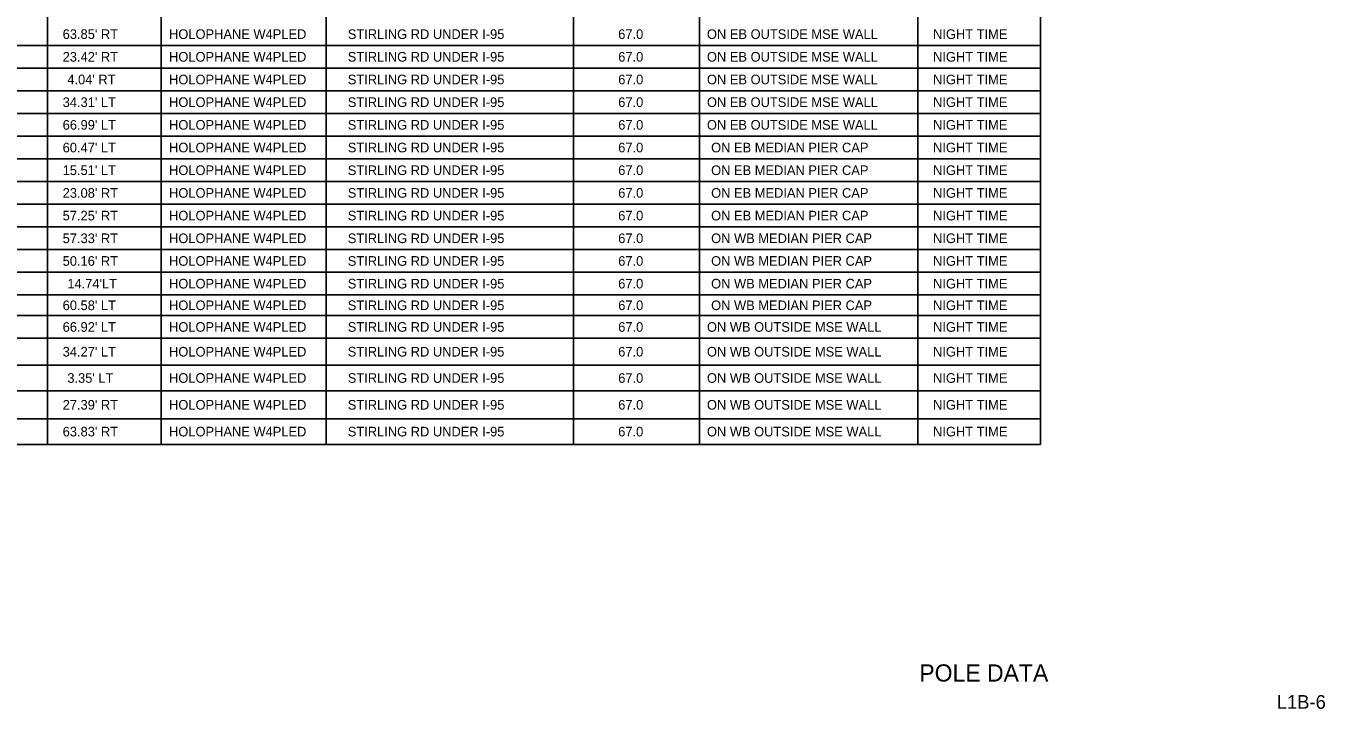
# Model space of a CAD drawing. Extents: x -816.7 to -800.9, y -2209.6 to -2187.8.
# Drawn here: x -810.38 to -800.93, y -2197.64 to -2192.68 of the extents above; entities that cross this region are included whole.
import ezdxf

# ---------------------------------------------------------------- set-up
doc = ezdxf.new("R2010")
doc.units = 0
for name, color, linetype in [('PlotBorder_dp', 7, 'Continuous'), ('SheetBorder_dp', 7, 'Continuous'), ('SheetLines_dp', 7, 'Continuous'), ('TextMinor', 7, 'Continuous'), ('TextMisc', 7, 'Continuous'), ('TextShtNo', 7, 'Continuous')]:
    doc.layers.add(name, color=color, linetype=linetype)

msp = doc.modelspace()

# ---------------------------------------------------------------- linework, layer by layer
at = {"layer": 'PlotBorder_dp'}
for p, q in [((-810.2186, -2188.1983), (-810.2186, -2195.7208)), ((-809.3936, -2188.1983), (-809.3936, -2195.7208)), ((-809.3936, -2188.1983), (-809.3936, -2195.7208)), ((-808.1936, -2188.1983), (-808.1936, -2195.7208)), ((-808.1936, -2188.1983), (-808.1936, -2195.7208)), ((-806.3936, -2188.1983), (-806.3936, -2195.7208)), ((-806.3936, -2188.1983), (-806.3936, -2195.7208)), ((-805.4786, -2188.1983), (-805.4786, -2195.7208)), ((-805.4786, -2188.1983), (-805.4786, -2195.7208)), ((-810.2186, -2189.5183), (-810.2186, -2195.7208))]:
    msp.add_line(p, q, dxfattribs=at)
at = {"layer": 'SheetLines_dp'}
for p, q in [((-802.9961, -2187.8233), (-802.9961, -2195.7208)), ((-803.8886, -2188.1983), (-803.8886, -2195.7208)), ((-803.8886, -2188.1983), (-803.8886, -2195.7208)), ((-813.0161, -2195.7208), (-802.9961, -2195.7208))]:
    msp.add_line(p, q, dxfattribs=at)
at = {"layer": 'TextMinor'}
for p, q in [((-813.0161, -2192.8183), (-802.9961, -2192.8183)), ((-813.0161, -2192.8183), (-802.9961, -2192.8183)), ((-813.0161, -2192.9833), (-802.9961, -2192.9833)), ((-813.0161, -2192.9833), (-802.9961, -2192.9833)), ((-813.0161, -2193.1483), (-802.9961, -2193.1483)), ((-813.0161, -2193.1483), (-802.9961, -2193.1483)), ((-813.0161, -2193.3133), (-802.9961, -2193.3133)), ((-813.0161, -2193.3133), (-802.9961, -2193.3133)), ((-813.0161, -2193.4783), (-802.9961, -2193.4783)), ((-813.0161, -2193.4783), (-802.9961, -2193.4783)), ((-813.0161, -2193.6433), (-802.9961, -2193.6433)), ((-813.0161, -2193.6433), (-802.9961, -2193.6433)), ((-813.0161, -2193.8083), (-802.9961, -2193.8083)), ((-813.0161, -2193.8083), (-802.9961, -2193.8083)), ((-813.0161, -2193.9733), (-802.9961, -2193.9733)), ((-813.0161, -2193.9733), (-802.9961, -2193.9733)), ((-813.0161, -2194.1383), (-802.9961, -2194.1383)), ((-813.0161, -2194.1383), (-802.9961, -2194.1383)), ((-813.0161, -2194.3033), (-802.9961, -2194.3033)), ((-813.0161, -2194.3033), (-802.9961, -2194.3033)), ((-813.0161, -2194.4683), (-802.9961, -2194.4683)), ((-813.0161, -2194.4683), (-802.9961, -2194.4683)), ((-813.0161, -2194.6333), (-802.9961, -2194.6333)), ((-813.0161, -2194.6333), (-802.9961, -2194.6333)), ((-813.0161, -2194.7833), (-802.9961, -2194.7833)), ((-813.0161, -2194.7833), (-802.9961, -2194.7833)), ((-813.0161, -2194.9483), (-802.9961, -2194.9483)), ((-813.0161, -2194.9483), (-802.9961, -2194.9483)), ((-813.0161, -2195.1433), (-802.9961, -2195.1433)), ((-813.0161, -2195.1433), (-802.9961, -2195.1433)), ((-813.0161, -2195.3308), (-802.9961, -2195.3308)), ((-813.0161, -2195.3308), (-802.9961, -2195.3308)), ((-813.0161, -2195.5333), (-802.9961, -2195.5333)), ((-813.0161, -2195.5333), (-802.9961, -2195.5333))]:
    msp.add_line(p, q, dxfattribs=at)

# ---------------------------------------------------------------- texts
at = {"layer": 'SheetBorder_dp'}
for s, p in [("63.85' RT", (-810.1092, -2192.7708)), ('HOLOPHANE W4PLED', (-809.3354, -2192.7708)), ('STIRLING RD UNDER I-95', (-808.0355, -2192.7708)), ('67.0', (-806.0686, -2192.7708)), ('ON EB OUTSIDE MSE WALL', (-805.4232, -2192.7708)), ('NIGHT TIME', (-803.7789, -2192.7708)), ("23.42' RT", (-810.1092, -2192.9358)), ('HOLOPHANE W4PLED', (-809.3354, -2192.9358)), ('STIRLING RD UNDER I-95', (-808.0355, -2192.9358)), ('67.0', (-806.0686, -2192.9358)), ('ON EB OUTSIDE MSE WALL', (-805.4232, -2192.9358)), ('NIGHT TIME', (-803.7789, -2192.9358)), ("4.04' RT", (-810.0753, -2193.1008)), ('HOLOPHANE W4PLED', (-809.3354, -2193.1008)), ('STIRLING RD UNDER I-95', (-808.0355, -2193.1008)), ('67.0', (-806.0686, -2193.1008)), ('ON EB OUTSIDE MSE WALL', (-805.4232, -2193.1008)), ('NIGHT TIME', (-803.7789, -2193.1008)), ("34.31' LT", (-810.1092, -2193.2658)), ('HOLOPHANE W4PLED', (-809.3354, -2193.2658)), ('STIRLING RD UNDER I-95', (-808.0355, -2193.2658)), ('67.0', (-806.0686, -2193.2658)), ('ON EB OUTSIDE MSE WALL', (-805.4232, -2193.2658)), ('NIGHT TIME', (-803.7789, -2193.2658)), ("66.99' LT", (-810.1092, -2193.4308)), ('HOLOPHANE W4PLED', (-809.3354, -2193.4308)), ('STIRLING RD UNDER I-95', (-808.0355, -2193.4308)), ('67.0', (-806.0686, -2193.4308)), ('ON EB OUTSIDE MSE WALL', (-805.4232, -2193.4308)), ('NIGHT TIME', (-803.7789, -2193.4308)), ("60.47' LT", (-810.1092, -2193.5958)), ('HOLOPHANE W4PLED', (-809.3354, -2193.5958)), ('STIRLING RD UNDER I-95', (-808.0355, -2193.5958)), ('67.0', (-806.0686, -2193.5958)), ('ON EB MEDIAN PIER CAP', (-805.3928, -2193.5958)), ('NIGHT TIME', (-803.7789, -2193.5958)), ("15.51' LT", (-810.1092, -2193.7608)), ('HOLOPHANE W4PLED', (-809.3354, -2193.7608)), ('STIRLING RD UNDER I-95', (-808.0355, -2193.7608)), ('67.0', (-806.0686, -2193.7608)), ('ON EB MEDIAN PIER CAP', (-805.3928, -2193.7608)), ('NIGHT TIME', (-803.7789, -2193.7608)), ("23.08' RT", (-810.1092, -2193.9258)), ('HOLOPHANE W4PLED', (-809.3354, -2193.9258)), ('STIRLING RD UNDER I-95', (-808.0355, -2193.9258)), ('67.0', (-806.0686, -2193.9258)), ('ON EB MEDIAN PIER CAP', (-805.3928, -2193.9258)), ('NIGHT TIME', (-803.7789, -2193.9258)), ("57.25' RT", (-810.1092, -2194.0908)), ('HOLOPHANE W4PLED', (-809.3354, -2194.0908)), ('STIRLING RD UNDER I-95', (-808.0355, -2194.0908)), ('67.0', (-806.0686, -2194.0908)), ('ON EB MEDIAN PIER CAP', (-805.3928, -2194.0908)), ('NIGHT TIME', (-803.7789, -2194.0908)), ("57.33' RT", (-810.1092, -2194.2558)), ('HOLOPHANE W4PLED', (-809.3354, -2194.2558)), ('STIRLING RD UNDER I-95', (-808.0355, -2194.2558)), ('67.0', (-806.0686, -2194.2558)), ('ON WB MEDIAN PIER CAP', (-805.3928, -2194.2558)), ('NIGHT TIME', (-803.7789, -2194.2558)), ("50.16' RT", (-810.1092, -2194.4208)), ('HOLOPHANE W4PLED', (-809.3354, -2194.4208)), ('STIRLING RD UNDER I-95', (-808.0355, -2194.4208)), ('67.0', (-806.0686, -2194.4208)), ('ON WB MEDIAN PIER CAP', (-805.3928, -2194.4208)), ('NIGHT TIME', (-803.7789, -2194.4208)), ("14.74'LT", (-810.0753, -2194.5858)), ('HOLOPHANE W4PLED', (-809.3354, -2194.5858)), ('STIRLING RD UNDER I-95', (-808.0355, -2194.5858)), ('67.0', (-806.0686, -2194.5858)), ('ON WB MEDIAN PIER CAP', (-805.3928, -2194.5858)), ('NIGHT TIME', (-803.7789, -2194.5858)), ("60.58' LT", (-810.1092, -2194.7433)), ('HOLOPHANE W4PLED', (-809.3354, -2194.7433)), ('STIRLING RD UNDER I-95', (-808.0355, -2194.7433)), ('67.0', (-806.0686, -2194.7433)), ('ON WB MEDIAN PIER CAP', (-805.3928, -2194.7433)), ('NIGHT TIME', (-803.7789, -2194.7433)), ("66.92' LT", (-810.1092, -2194.9008)), ('HOLOPHANE W4PLED', (-809.3354, -2194.9008)), ('STIRLING RD UNDER I-95', (-808.0355, -2194.9008)), ('67.0', (-806.0686, -2194.9008)), ('ON WB OUTSIDE MSE WALL', (-805.4232, -2194.9008)), ('NIGHT TIME', (-803.7789, -2194.9008)), ("34.27' LT", (-810.1092, -2195.0808)), ('HOLOPHANE W4PLED', (-809.3354, -2195.0808)), ('STIRLING RD UNDER I-95', (-808.0355, -2195.0808)), ('67.0', (-806.0686, -2195.0808)), ('ON WB OUTSIDE MSE WALL', (-805.4232, -2195.0808)), ('NIGHT TIME', (-803.7789, -2195.0808)), ("3.35' LT", (-810.0753, -2195.272)), ('HOLOPHANE W4PLED', (-809.3354, -2195.272)), ('STIRLING RD UNDER I-95', (-808.0355, -2195.272)), ('67.0', (-806.0686, -2195.272)), ('ON WB OUTSIDE MSE WALL', (-805.4232, -2195.272)), ('NIGHT TIME', (-803.7789, -2195.272)), ("27.39' RT", (-810.1092, -2195.467)), ('HOLOPHANE W4PLED', (-809.3354, -2195.467)), ('STIRLING RD UNDER I-95', (-808.0355, -2195.467)), ('67.0', (-806.0686, -2195.467)), ('ON WB OUTSIDE MSE WALL', (-805.4232, -2195.467)), ('NIGHT TIME', (-803.7789, -2195.467)), ("63.83' RT", (-810.1092, -2195.662)), ('HOLOPHANE W4PLED', (-809.3354, -2195.662)), ('STIRLING RD UNDER I-95', (-808.0355, -2195.662)), ('67.0', (-806.0686, -2195.662)), ('ON WB OUTSIDE MSE WALL', (-805.4232, -2195.662)), ('NIGHT TIME', (-803.7789, -2195.662))]:
    msp.add_text(s, height=0.07, dxfattribs=at).set_placement(p)
at = {"layer": 'TextMisc'}
msp.add_text('POLE DATA', height=0.125, dxfattribs=at).set_placement((-803.8787, -2197.445))
at = {"layer": 'TextShtNo'}
msp.add_text('L1B-6  ', height=0.1, dxfattribs=at).set_placement((-801.2789, -2197.6434))

doc.saveas('drawing.dxf')
